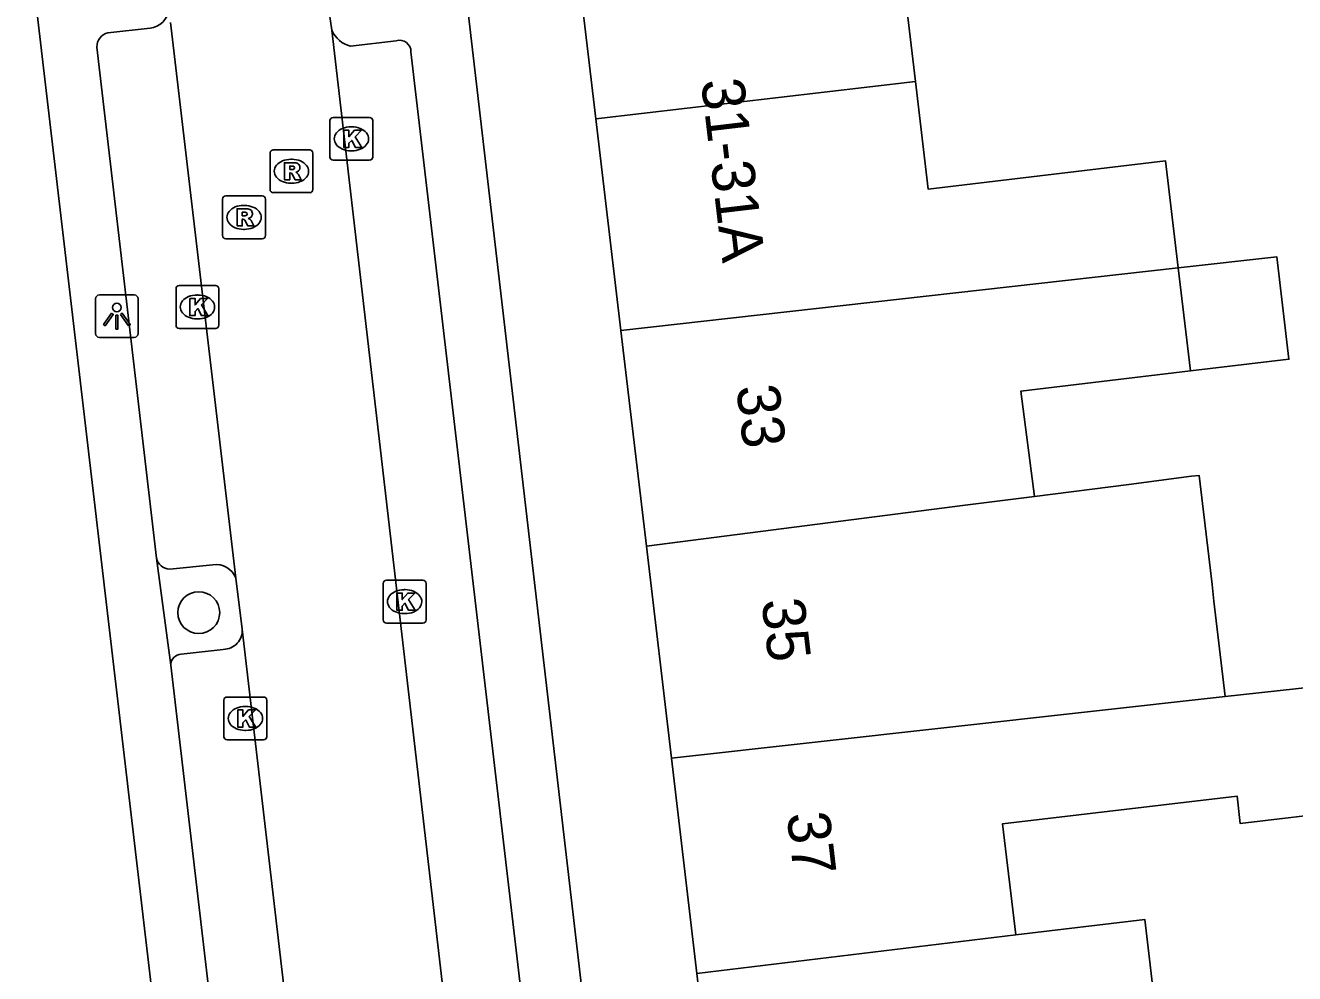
# Model space of a CAD drawing. Extents: x 162250 to 162654, y 380744 to 381605.
# Drawn here: x 162453.35 to 162482.99, y 381013.48 to 381035.63 of the extents above; entities that cross this region are included whole.
import ezdxf

# ---------------------------------------------------------------- set-up
doc = ezdxf.new("R2010")
doc.units = 0
for name, color, linetype in [('IMGEO_Boom', 7, 'Continuous'), ('IMGEO_Kolk', 7, 'Continuous'), ('IMGEO_Lichtpunt', 7, 'Continuous'), ('IMGEO_Pand', 7, 'Continuous'), ('IMGEO_Pand_nummerreeks', 7, 'Continuous'), ('IMGEO_Parkeervlak_open', 7, 'Continuous'), ('IMGEO_Rijbaan_lokaal_open', 7, 'Continuous'), ('IMGEO_Rioolput', 7, 'Continuous'), ('IMGEO_Voetpad_open', 7, 'Continuous')]:
    doc.layers.add(name, color=color, linetype=linetype)

msp = doc.modelspace()

# ---------------------------------------------------------------- linework, layer by layer
at = {"layer": 'IMGEO_Boom'}
msp.add_circle((162457.394, 381021.911), 0.489, dxfattribs=at)
at = {"layer": 'IMGEO_Kolk'}
for p, q in [((162460.534, 381033.48), (162461.386, 381033.48)), ((162460.459, 381032.554), (162460.459, 381033.406)), ((162460.947, 381033.26), (162460.972, 381033.26)), ((162461.46, 381033.406), (162461.46, 381032.554)), ((162460.97, 381032.7), (162460.945, 381032.7)), ((162461.386, 381032.48), (162460.534, 381032.48)), ((162456.863, 381028.626), (162456.863, 381029.478)), ((162456.938, 381029.552), (162457.79, 381029.552)), ((162457.351, 381029.332), (162457.376, 381029.332)), ((162457.864, 381029.478), (162457.864, 381028.626)), ((162457.374, 381028.772), (162457.349, 381028.772)), ((162457.79, 381028.552), (162456.938, 381028.552)), ((162461.702, 381021.742), (162461.702, 381022.594)), ((162461.777, 381022.668), (162462.629, 381022.668)), ((162462.703, 381022.594), (162462.703, 381021.742)), ((162462.19, 381022.448), (162462.215, 381022.448)), ((162462.213, 381021.888), (162462.188, 381021.888)), ((162462.629, 381021.668), (162461.777, 381021.668)), ((162457.983, 381019.013), (162457.983, 381019.865)), ((162458.058, 381019.939), (162458.91, 381019.939)), ((162458.984, 381019.865), (162458.984, 381019.013)), ((162458.471, 381019.719), (162458.496, 381019.719)), ((162458.91, 381018.939), (162458.058, 381018.939)), ((162458.494, 381019.159), (162458.469, 381019.159))]:
    msp.add_line(p, q, dxfattribs=at)
for points in [[(162460.534, 381033.48), (162461.386, 381033.48)], [(162460.459, 381032.554), (162460.459, 381033.406)], [(162460.78, 381033.18), (162460.903, 381033.18), (162460.903, 381033.029), (162461.033, 381033.18), (162461.197, 381033.18), (162461.051, 381033.029), (162461.204, 381032.78), (162461.052, 381032.78), (162460.967, 381032.944), (162460.903, 381032.877), (162460.903, 381032.78), (162460.78, 381032.78), (162460.78, 381033.18)], [(162461.46, 381033.406), (162461.46, 381032.554)], [(162461.386, 381032.48), (162460.534, 381032.48)], [(162456.863, 381028.626), (162456.863, 381029.478)], [(162456.938, 381029.552), (162457.79, 381029.552)], [(162457.864, 381029.478), (162457.864, 381028.626)], [(162457.184, 381029.252), (162457.307, 381029.252), (162457.307, 381029.101), (162457.437, 381029.252), (162457.601, 381029.252), (162457.455, 381029.101), (162457.608, 381028.852), (162457.456, 381028.852), (162457.371, 381029.016), (162457.307, 381028.949), (162457.307, 381028.852), (162457.184, 381028.852), (162457.184, 381029.252)], [(162457.79, 381028.552), (162456.938, 381028.552)], [(162461.702, 381021.742), (162461.702, 381022.594)], [(162461.777, 381022.668), (162462.629, 381022.668)], [(162462.703, 381022.594), (162462.703, 381021.742)], [(162462.023, 381022.368), (162462.146, 381022.368), (162462.146, 381022.217), (162462.276, 381022.368), (162462.44, 381022.368), (162462.294, 381022.217), (162462.447, 381021.968), (162462.295, 381021.968), (162462.21, 381022.132), (162462.146, 381022.065), (162462.146, 381021.968), (162462.023, 381021.968), (162462.023, 381022.368)], [(162462.629, 381021.668), (162461.777, 381021.668)], [(162457.983, 381019.013), (162457.983, 381019.865)], [(162458.058, 381019.939), (162458.91, 381019.939)], [(162458.984, 381019.865), (162458.984, 381019.013)], [(162458.304, 381019.639), (162458.427, 381019.639), (162458.427, 381019.488), (162458.557, 381019.639), (162458.721, 381019.639), (162458.575, 381019.488), (162458.728, 381019.239), (162458.576, 381019.239), (162458.491, 381019.403), (162458.427, 381019.336), (162458.427, 381019.239), (162458.304, 381019.239), (162458.304, 381019.639)], [(162458.91, 381018.939), (162458.058, 381018.939)]]:
    msp.add_lwpolyline(points, dxfattribs=at)
for centre, start, end in [((162460.536, 381033.404), 91.552, 178.448), ((162460.536, 381033.404), 91.552, 178.448), ((162461.384, 381033.404), 1.552, 88.448), ((162461.384, 381033.404), 1.552, 88.448), ((162460.536, 381032.556), 181.552, 268.448), ((162460.536, 381032.556), 181.552, 268.448), ((162461.384, 381032.556), 271.552, 358.448), ((162461.384, 381032.556), 271.552, 358.448), ((162456.94, 381029.476), 91.552, 178.448), ((162456.94, 381029.476), 91.552, 178.448), ((162457.788, 381029.476), 1.552, 88.448), ((162457.788, 381029.476), 1.552, 88.448), ((162456.94, 381028.628), 181.552, 268.448), ((162456.94, 381028.628), 181.552, 268.448), ((162457.788, 381028.628), 271.552, 358.448), ((162457.788, 381028.628), 271.552, 358.448), ((162461.779, 381022.592), 91.552, 178.448), ((162461.779, 381022.592), 91.552, 178.448), ((162462.627, 381022.592), 1.552, 88.448), ((162462.627, 381022.592), 1.552, 88.448), ((162461.779, 381021.744), 181.552, 268.448), ((162461.779, 381021.744), 181.552, 268.448), ((162462.627, 381021.744), 271.552, 358.448), ((162462.627, 381021.744), 271.552, 358.448), ((162458.06, 381019.863), 91.552, 178.448), ((162458.06, 381019.863), 91.552, 178.448), ((162458.908, 381019.863), 1.552, 88.448), ((162458.908, 381019.863), 1.552, 88.448), ((162458.06, 381019.015), 181.552, 268.448), ((162458.06, 381019.015), 181.552, 268.448), ((162458.908, 381019.015), 271.552, 358.448), ((162458.908, 381019.015), 271.552, 358.448)]:
    msp.add_arc(centre, 0.0765, start, end, dxfattribs=at)
for centre, major_axis, ratio, start_param, end_param in [((162460.946, 381032.98), (-0.387, 0.002), 0.722429, 4.712389, 7.853982), ((162460.971, 381032.98), (-0.39, 0.002), 0.717154, 1.570796, 4.712389), ((162457.35, 381029.052), (-0.387, 0.002), 0.722429, 4.712389, 7.853982), ((162457.375, 381029.052), (-0.39, 0.002), 0.717154, 1.570796, 4.712389), ((162462.189, 381022.168), (-0.387, 0.002), 0.722429, 4.712389, 7.853982), ((162462.214, 381022.168), (-0.39, 0.002), 0.717154, 1.570796, 4.712389), ((162458.47, 381019.439), (-0.387, 0.002), 0.722429, 4.712389, 7.853982), ((162458.495, 381019.439), (-0.39, 0.002), 0.717154, 1.570796, 4.712389)]:
    msp.add_ellipse(centre, major_axis=major_axis, ratio=ratio, start_param=start_param, end_param=end_param, dxfattribs=at)
at = {"layer": 'IMGEO_Lichtpunt'}
for p, q in [((162455.885, 381029.336), (162455.077, 381029.336)), ((162455.885, 381029.336), (162455.077, 381029.336)), ((162454.983, 381029.241), (162454.983, 381028.434)), ((162454.983, 381029.241), (162454.983, 381028.434)), ((162455.979, 381028.434), (162455.979, 381029.241)), ((162455.979, 381028.434), (162455.979, 381029.241)), ((162455.077, 381028.34), (162455.885, 381028.34)), ((162455.077, 381028.34), (162455.885, 381028.34))]:
    msp.add_line(p, q, dxfattribs=at)
for points in [[(162455.357, 381028.905), (162455.396, 381028.877), (162455.208, 381028.615), (162455.17, 381028.642), (162455.357, 381028.905)], [(162455.459, 381028.857), (162455.506, 381028.857), (162455.506, 381028.535), (162455.459, 381028.535), (162455.459, 381028.857)], [(162455.569, 381028.877), (162455.607, 381028.904), (162455.794, 381028.642), (162455.755, 381028.614), (162455.569, 381028.877)]]:
    msp.add_lwpolyline(points, dxfattribs=at)
msp.add_circle((162455.482, 381029.039), 0.0994, dxfattribs=at)
for centre, start, end in [((162455.077, 381029.241), 90, 180), ((162455.077, 381029.241), 90, 180), ((162455.885, 381029.241), 0, 90), ((162455.885, 381029.241), 0, 90), ((162455.077, 381028.434), 180, 270), ((162455.077, 381028.434), 180, 270), ((162455.885, 381028.434), 270, 0), ((162455.885, 381028.434), 270, 360)]:
    msp.add_arc(centre, 0.0946, start, end, dxfattribs=at)
at = {"layer": 'IMGEO_Pand'}
for points in [[(162479.095, 381039.889), (162479.382, 381037.465), (162473.836, 381036.809), (162474.131, 381034.32)], [(162466.67, 381033.444), (162466.095, 381038.309)], [(162466.67, 381033.444), (162474.131, 381034.32)], [(162474.131, 381034.32), (162474.428, 381031.807), (162479.974, 381032.463), (162480.269, 381029.968)], [(162467.253, 381028.502), (162466.67, 381033.444)], [(162480.554, 381027.557), (162482.856, 381027.829), (162482.572, 381030.227), (162480.269, 381029.968)], [(162480.269, 381029.968), (162467.253, 381028.502)], [(162480.269, 381029.968), (162480.554, 381027.557)], [(162467.848, 381023.463), (162467.253, 381028.502)], [(162480.554, 381027.557), (162476.598, 381027.089), (162476.914, 381024.625)], [(162476.914, 381024.625), (162479.116, 381024.908), (162480.582, 381025.096), (162480.758, 381025.118), (162481.06, 381022.567), (162481.106, 381022.176), (162481.37, 381019.95)], [(162467.848, 381023.463), (162475.296, 381024.418), (162476.914, 381024.625)], [(162468.432, 381018.509), (162467.848, 381023.463)], [(162481.37, 381019.95), (162483.867, 381020.228), (162484.215, 381017.278), (162481.721, 381016.983), (162481.645, 381017.624), (162476.169, 381016.977), (162476.476, 381014.38)], [(162468.432, 381018.509), (162481.37, 381019.95)], [(162469.025, 381013.484), (162468.432, 381018.509)], [(162476.476, 381014.38), (162479.49, 381014.742), (162479.765, 381012.423), (162482.276, 381012.72)], [(162469.025, 381013.484), (162476.476, 381014.38)], [(162469.621, 381008.437), (162469.025, 381013.484)]]:
    msp.add_lwpolyline(points, dxfattribs=at)
at = {"layer": 'IMGEO_Parkeervlak_open'}
for points in [[(162457.723, 381023.031), (162456.715, 381022.926)], [(162457.968, 381021.052), (162456.986, 381020.94)]]:
    msp.add_lwpolyline(points, dxfattribs=at)
for centre, radius, start, end in [((162456.723, 381023.25), 0.324, 191.3673, 268.6589), ((162457.797, 381022.538), 0.498, 21.286, 98.4929), ((162457.961, 381021.503), 0.451, 270.8372, 2.6645), ((162456.992, 381020.689), 0.251, 91.3629, 180.9286)]:
    msp.add_arc(centre, radius, start, end, dxfattribs=at)
at = {"layer": 'IMGEO_Rijbaan_lokaal_open'}
for points in [[(162460.5, 381035.516), (162460.418, 381036.093)], [(162458.261, 381022.719), (162456.733, 381035.695)], [(162460.5, 381035.516), (162463.312, 381011.262)], [(162458.412, 381021.524), (162458.261, 381022.719)], [(162461.237, 380997.285), (162458.412, 381021.524)]]:
    msp.add_lwpolyline(points, dxfattribs=at)
at = {"layer": 'IMGEO_Rioolput'}
for p, q in [((162459.059, 381031.797), (162459.059, 381032.649)), ((162459.134, 381032.723), (162459.986, 381032.723)), ((162460.06, 381032.649), (162460.06, 381031.797)), ((162459.547, 381032.503), (162459.572, 381032.503)), ((162459.986, 381031.723), (162459.134, 381031.723)), ((162459.57, 381031.943), (162459.545, 381031.943)), ((162457.951, 381030.719), (162457.951, 381031.571)), ((162458.026, 381031.645), (162458.878, 381031.645)), ((162458.439, 381031.425), (162458.464, 381031.425)), ((162458.952, 381031.571), (162458.952, 381030.719)), ((162458.462, 381030.865), (162458.437, 381030.865)), ((162458.878, 381030.645), (162458.026, 381030.645))]:
    msp.add_line(p, q, dxfattribs=at)
for points in [[(162459.059, 381031.797), (162459.059, 381032.649)], [(162459.134, 381032.723), (162459.986, 381032.723)], [(162460.06, 381032.649), (162460.06, 381031.797)], [(162459.648, 381032.421), (162459.396, 381032.423), (162459.396, 381032.023)], [(162459.574, 381032.342), (162459.52, 381032.342), (162459.52, 381032.261)], [(162459.52, 381032.261), (162459.572, 381032.261)], [(162459.396, 381032.023), (162459.52, 381032.023), (162459.52, 381032.185), (162459.531, 381032.185)], [(162459.578, 381032.156), (162459.649, 381032.023), (162459.789, 381032.023), (162459.724, 381032.149)], [(162459.986, 381031.723), (162459.134, 381031.723)], [(162457.951, 381030.719), (162457.951, 381031.571)], [(162458.026, 381031.645), (162458.878, 381031.645)], [(162458.952, 381031.571), (162458.952, 381030.719)], [(162458.54, 381031.343), (162458.288, 381031.345), (162458.288, 381030.945)], [(162458.288, 381030.945), (162458.412, 381030.945), (162458.412, 381031.107), (162458.423, 381031.107)], [(162458.466, 381031.264), (162458.412, 381031.264), (162458.412, 381031.183)], [(162458.412, 381031.183), (162458.464, 381031.183)], [(162458.47, 381031.078), (162458.541, 381030.945), (162458.681, 381030.945), (162458.616, 381031.071)], [(162458.878, 381030.645), (162458.026, 381030.645)]]:
    msp.add_lwpolyline(points, dxfattribs=at)
for centre, radius, start, end in [((162459.136, 381032.647), 0.0765, 91.552, 178.448), ((162459.136, 381032.647), 0.0765, 91.552, 178.448), ((162459.984, 381032.647), 0.0765, 1.552, 88.448), ((162459.984, 381032.647), 0.0765, 1.552, 88.448), ((162459.556, 381032.45), 0.19, 274.7715, 282.9687), ((162459.58, 381032.246), 0.0964, 77.0061, 93.1865), ((162459.594, 381032.303), 0.0378, 276.6634, 79.6772), ((162459.647, 381032.311), 0.109, 350.3612, 89.416), ((162459.645, 381032.311), 0.112, 277.5842, 350.9817), ((162459.53, 381032.132), 0.0533, 26.0293, 88.6989), ((162459.629, 381032.096), 0.108, 29.5134, 73.7905), ((162459.136, 381031.799), 0.0765, 181.552, 268.448), ((162459.136, 381031.799), 0.0765, 181.552, 268.448), ((162459.984, 381031.799), 0.0765, 271.552, 358.448), ((162459.984, 381031.799), 0.0765, 271.552, 358.448), ((162458.028, 381031.569), 0.0765, 91.552, 178.448), ((162458.028, 381031.569), 0.0765, 91.552, 178.448), ((162458.876, 381031.569), 0.0765, 1.552, 88.448), ((162458.876, 381031.569), 0.0765, 1.552, 88.448), ((162458.422, 381031.054), 0.0533, 26.0293, 88.6989), ((162458.448, 381031.372), 0.19, 274.7715, 282.9687), ((162458.472, 381031.168), 0.0964, 77.0061, 93.1865), ((162458.486, 381031.225), 0.0378, 276.6634, 79.6772), ((162458.539, 381031.233), 0.109, 350.3612, 89.416), ((162458.537, 381031.233), 0.112, 277.5842, 350.9817), ((162458.521, 381031.018), 0.108, 29.5134, 73.7905), ((162458.028, 381030.721), 0.0765, 181.552, 268.448), ((162458.028, 381030.721), 0.0765, 181.552, 268.448), ((162458.876, 381030.721), 0.0765, 271.552, 358.448), ((162458.876, 381030.721), 0.0765, 271.552, 358.448)]:
    msp.add_arc(centre, radius, start, end, dxfattribs=at)
for centre, major_axis, ratio, start_param, end_param in [((162459.546, 381032.223), (-0.387, 0.002), 0.722429, 4.712389, 7.853982), ((162459.571, 381032.223), (-0.39, 0.002), 0.717154, 1.570796, 4.712389), ((162458.438, 381031.145), (-0.387, 0.002), 0.722429, 4.712389, 7.853982), ((162458.463, 381031.145), (-0.39, 0.002), 0.717154, 1.570796, 4.712389)]:
    msp.add_ellipse(centre, major_axis=major_axis, ratio=ratio, start_param=start_param, end_param=end_param, dxfattribs=at)
at = {"layer": 'IMGEO_Voetpad_open'}
for points in [[(162455.21, 381107.834), (162462.62, 381045.107), (162467.864, 381000), (162469.785, 380983.331)], [(162460.106, 380980.583), (162457.834, 381000), (162450.879, 381059.205), (162445.423, 381105.014)], [(162455.268, 381035.458), (162456.256, 381035.567)], [(162462.006, 381035.272), (162460.942, 381035.142)], [(162456.405, 381023.186), (162455.014, 381035.125)], [(162465.026, 381012.162), (162462.351, 381035.014)], [(162456.741, 381020.685), (162456.405, 381023.186)], [(162459.425, 380997.701), (162456.741, 381020.685)]]:
    msp.add_lwpolyline(points, dxfattribs=at)
for centre, radius, start, end in [((162456.206, 381036.06), 0.496, 275.7723, 352.6508), ((162461.11, 381035.789), 0.668, 204.0988, 255.4285), ((162455.35, 381035.132), 0.336, 104.1767, 181.1532), ((162462.083, 381035.015), 0.268, 359.8243, 106.5955)]:
    msp.add_arc(centre, radius, start, end, dxfattribs=at)

# ---------------------------------------------------------------- texts
at = {"layer": 'IMGEO_Pand_nummerreeks'}
for s, rotation, p in [('31-31A', 276.7591, (162469.122, 381034.341)), ('33', 276.732, (162469.946, 381027.189)), ('35', 276.732, (162470.535, 381022.197)), ('37', 276.732, (162471.124, 381017.205))]:
    msp.add_text(s, height=1, rotation=rotation, dxfattribs=at).set_placement(p)

doc.saveas('drawing.dxf')
